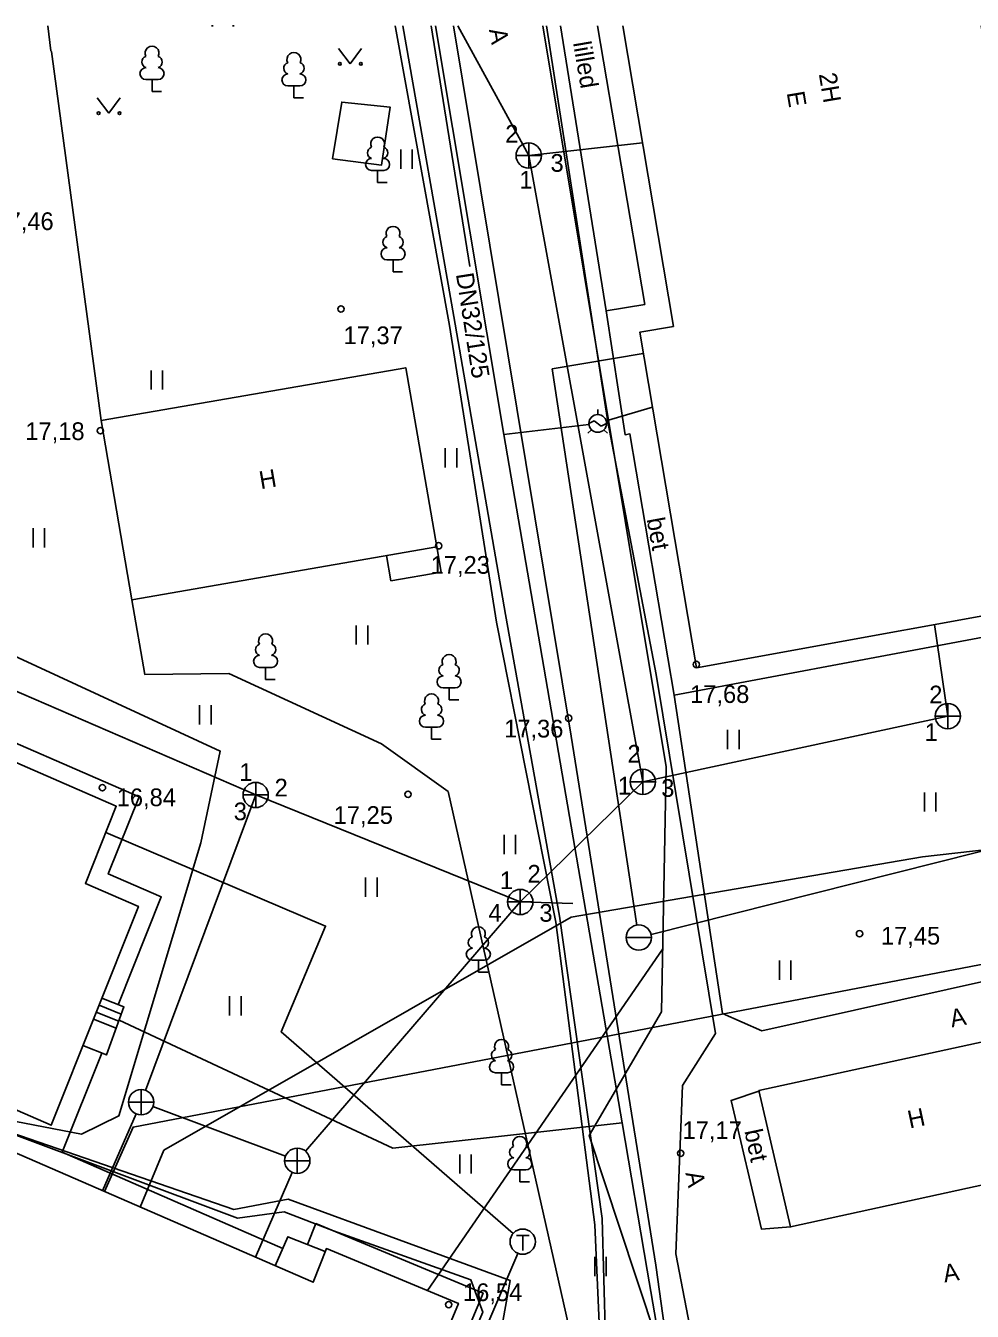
# Model space of a CAD drawing. Extents: x 713540 to 713867, y 6589774 to 6590061.
# Drawn here: x 713614.3 to 713651.7, y 6590009.8 to 6590060.6 of the extents above; entities that cross this region are included whole.
import ezdxf

# ---------------------------------------------------------------- set-up
doc = ezdxf.new("R2010")
doc.units = 0
for name, color, linetype in [('AED', 7, 'Continuous'), ('HALJASTUS', 7, 'Continuous'), ('HOONE', 7, 'Continuous'), ('HOONEDET', 7, 'Continuous'), ('KKAEV', 7, 'Continuous'), ('KORGUS', 7, 'Continuous'), ('KTRASS', 7, 'Continuous'), ('MPKAABEL', 7, 'Continuous'), ('PUU', 7, 'Continuous'), ('SITRASS', 7, 'Continuous'), ('TEE', 7, 'Continuous'), ('TKAEV', 7, 'Continuous'), ('TORU NR', 7, 'Continuous'), ('TTRASS', 7, 'Continuous'), ('VKAEV', 7, 'Continuous'), ('VTRASS', 7, 'Continuous')]:
    doc.layers.add(name, color=color, linetype=linetype)

msp = doc.modelspace()

# ---------------------------------------------------------------- linework, layer by layer
at = {"layer": 'AED'}
for points in [[(713617.266, 6590045.028), (713615.306, 6590059.611), (713615.285, 6590059.641), (713615.156, 6590060.636)], [(713618.488, 6590037.946), (713619.001, 6590034.99), (713622.312, 6590035.031), (713628.353, 6590032.257), (713630.993, 6590030.365), (713635.85, 6590008.82)]]:
    msp.add_lwpolyline(points, dxfattribs=at)
at = {"layer": 'HALJASTUS'}
for p, q in [((713626.647, 6590059.737), (713627.11, 6590059.13)), ((713627.11, 6590059.13), (713627.556, 6590059.737)), ((713617.107, 6590057.787), (713617.57, 6590057.18)), ((713617.57, 6590057.18), (713618.016, 6590057.787)), ((713629.111, 6590055.745), (713629.111, 6590054.984)), ((713629.567, 6590055.745), (713629.567, 6590054.984)), ((713619.246, 6590047.013), (713619.246, 6590046.252)), ((713619.701, 6590047.013), (713619.701, 6590046.252)), ((713630.872, 6590043.942), (713630.872, 6590043.181)), ((713631.327, 6590043.942), (713631.327, 6590043.181)), ((713614.579, 6590040.772), (713614.579, 6590040.011)), ((713615.035, 6590040.772), (713615.035, 6590040.011)), ((713627.351, 6590036.937), (713627.351, 6590036.176)), ((713627.806, 6590036.937), (713627.806, 6590036.176)), ((713621.164, 6590033.778), (713621.164, 6590033.017)), ((713621.619, 6590033.778), (713621.619, 6590033.017)), ((713642.032, 6590032.802), (713642.032, 6590032.041)), ((713642.488, 6590032.802), (713642.488, 6590032.041)), ((713649.814, 6590030.335), (713649.814, 6590029.574)), ((713650.269, 6590030.335), (713650.269, 6590029.574)), ((713633.198, 6590028.657), (713633.198, 6590027.895)), ((713633.653, 6590028.657), (713633.653, 6590027.895)), ((713627.724, 6590026.973), (713627.724, 6590026.212)), ((713628.179, 6590026.973), (713628.179, 6590026.212)), ((713644.082, 6590023.687), (713644.082, 6590022.925)), ((713644.537, 6590023.687), (713644.537, 6590022.925)), ((713622.348, 6590022.28), (713622.348, 6590021.519)), ((713622.803, 6590022.28), (713622.803, 6590021.519)), ((713631.444, 6590016.028), (713631.444, 6590015.267)), ((713631.899, 6590016.028), (713631.899, 6590015.267)), ((713636.784, 6590011.978), (713636.784, 6590011.217)), ((713637.239, 6590011.978), (713637.239, 6590011.217))]:
    msp.add_line(p, q, dxfattribs=at)
msp.add_lwpolyline([(713631.848, 6590051.113), (713630.32, 6590060.636)], dxfattribs=at)
for centre in [(713626.709, 6590059.13), (713627.538, 6590059.13), (713617.169, 6590057.18), (713617.998, 6590057.18)]:
    msp.add_circle(centre, 0.055, dxfattribs=at)
for centre in [(713621.669, 6590060.68), (713622.498, 6590060.68)]:
    msp.add_arc(centre, 0.055, 232.8853, 307.1147, dxfattribs=at)
at = {"layer": 'HOONE'}
for p, q in [((713636.55, 6590044.916), (713636.762, 6590045.022)), ((713636.762, 6590045.022), (713637.039, 6590044.814)), ((713636.9, 6590045.268), (713636.9, 6590045.465)), ((713636.653, 6590044.67), (713636.513, 6590044.531)), ((713637.039, 6590044.814), (713637.25, 6590044.92)), ((713637.148, 6590044.67), (713637.287, 6590044.531))]:
    msp.add_line(p, q, dxfattribs=at)
for points in [[(713630.482, 6590060.636), (713633.183, 6590044.481), (713637.86, 6590017.28), (713638.858, 6590011.457), (713641.66, 6589995.12)], [(713637.89, 6590060.636), (713639.902, 6590048.748)], [(713639.902, 6590048.748), (713638.559, 6590048.521), (713640.803, 6590035.264), (713657.339, 6590038.264), (713655.499, 6590048.497), (713654.156, 6590048.27), (713652.063, 6590060.636)], [(713617.266, 6590045.028), (713629.313, 6590047.119), (713630.535, 6590040.036), (713618.488, 6590037.946), (713617.266, 6590045.028)], [(713637.236, 6590045.018), (713639.06, 6590045.56)], [(713633.183, 6590044.481), (713636.553, 6590044.877)], [(713613.137, 6590018.115), (713615.293, 6590017.178), (713618.744, 6590025.83), (713616.649, 6590026.74), (713617.865, 6590029.789), (713611.861, 6590032.397)], [(713616.549, 6590020.329), (713617.479, 6590019.958), (713618.167, 6590021.858), (713617.298, 6590022.205)], [(713617.978, 6590021.334), (713628.8, 6590016.27), (713637.86, 6590017.28)], [(713643.269, 6590018.555), (713655.327, 6590021.172), (713656.52, 6590015.784), (713644.523, 6590013.163), (713643.269, 6590018.555)], [(713611.945, 6590002.466), (713620.997, 6589998.591), (713623.828, 6590005.205), (713628.509, 6590003.201), (713631.396, 6590010.137), (713626.176, 6590012.308), (713625.646, 6590010.977), (713612.515, 6590016.682)], [(713624.152, 6590011.626), (713624.651, 6590012.773), (713626.127, 6590012.184)]]:
    msp.add_lwpolyline(points, dxfattribs=at)
msp.add_circle((713636.9, 6590044.918), 0.35, dxfattribs=at)
at = {"layer": 'HOONEDET'}
for p, q in [((713617.963, 6590021.294), (713617.075, 6590021.648)), ((713618.065, 6590021.576), (713617.187, 6590021.926)), ((713617.861, 6590021.011), (713616.964, 6590021.369))]:
    msp.add_line(p, q, dxfattribs=at)
msp.add_lwpolyline([(713625.431, 6590012.462), (713625.762, 6590013.293), (713632.366, 6590010.546), (713628.89, 6590002.231), (713623.97, 6590004.19)], dxfattribs=at)
at = {"layer": 'KKAEV'}
for p, q in [((713634.172, 6590055.004), (713634.172, 6590056.004)), ((713633.672, 6590055.504), (713634.672, 6590055.504)), ((713650.741, 6590032.85), (713650.741, 6590033.85)), ((713650.241, 6590033.35), (713651.241, 6590033.35)), ((713638.683, 6590030.252), (713638.683, 6590031.252)), ((713638.183, 6590030.752), (713639.183, 6590030.752)), ((713622.878, 6590030.232), (713623.878, 6590030.232)), ((713623.378, 6590029.732), (713623.378, 6590030.732)), ((713633.839, 6590025.503), (713633.839, 6590026.503)), ((713633.339, 6590026.003), (713634.339, 6590026.003)), ((713618.849, 6590017.591), (713618.849, 6590018.591)), ((713618.349, 6590018.091), (713619.349, 6590018.091)), ((713625.024, 6590015.276), (713625.024, 6590016.276)), ((713624.524, 6590015.776), (713625.524, 6590015.776))]:
    msp.add_line(p, q, dxfattribs=at)
for centre in [(713634.172, 6590055.504), (713650.741, 6590033.35), (713638.683, 6590030.752), (713623.378, 6590030.232), (713633.839, 6590026.003), (713618.849, 6590018.091), (713625.024, 6590015.776)]:
    msp.add_circle(centre, 0.5, dxfattribs=at)
at = {"layer": 'KORGUS'}
for centre in [(713626.75, 6590049.44), (713617.24, 6590044.63), (713630.61, 6590040.08), (713640.8, 6590035.39), (713635.75, 6590033.27), (713617.32, 6590030.52), (713629.4, 6590030.26), (713647.25, 6590024.75), (713640.18, 6590016.07), (713631.01, 6590010.09)]:
    msp.add_circle(centre, 0.125, dxfattribs=at)
at = {"layer": 'KTRASS'}
for p, q in [((713634.172, 6590055.504), (713631.371, 6590060.636)), ((713634.172, 6590055.504), (713638.674, 6590056.003)), ((713638.683, 6590030.752), (713634.172, 6590055.504)), ((713607.872, 6590036.944), (713623.378, 6590030.232)), ((713650.741, 6590033.35), (713650.209, 6590036.971)), ((713638.683, 6590030.752), (713650.741, 6590033.35)), ((713633.839, 6590026.003), (713638.683, 6590030.752)), ((713623.378, 6590030.232), (713619.024, 6590018.559)), ((713623.378, 6590030.232), (713633.839, 6590026.003)), ((713633.839, 6590026.003), (713625.351, 6590016.154)), ((713633.839, 6590026.003), (713635.913, 6590025.949))]:
    msp.add_line(p, q, dxfattribs=at)
for points in [[(713618.65, 6590017.632), (713617.329, 6590014.591)], [(713619.317, 6590017.915), (713624.556, 6590015.951)], [(713624.825, 6590015.317), (713623.369, 6590011.966)]]:
    msp.add_lwpolyline(points, dxfattribs=at)
at = {"layer": 'MPKAABEL'}
for points in [[(713634.872, 6590060.636), (713637.296, 6590044.981), (713639.214, 6590034.99), (713641.55, 6590020.81), (713640.247, 6590018.756), (713639.99, 6590012.096), (713640.67, 6590008.54), (713653.54, 6589985.5)], [(713563.12, 6590039.09), (713578.092, 6590032.827), (713580.05, 6590031.785), (713583.09, 6590031.071), (713588.688, 6590044.404), (713590.239, 6590045.736), (713594.584, 6590044.316), (713608.321, 6590038.279), (713621.981, 6590031.97), (713621.208, 6590028.335), (713617.972, 6590017.545), (713616.488, 6590016.829), (713613.482, 6590017.411)], [(713613.314, 6590017.025), (713622.509, 6590013.848), (713624.668, 6590014.258), (713633.443, 6590011.043), (713632.914, 6590008.103), (713628.469, 6589990.573), (713626.542, 6589984.315), (713631.711, 6589980.868), (713636.285, 6589978.421)], [(713631.696, 6590008.26), (713632.361, 6590009.786), (713631.878, 6590011.07), (713626.458, 6590013.001), (713624.501, 6590013.754), (713622.661, 6590013.508), (713613.306, 6590017.006)]]:
    msp.add_lwpolyline(points, dxfattribs=at)
at = {"layer": 'PUU'}
for p, q in [((713619.52, 6590058.505), (713619.04, 6590058.505)), ((713619.28, 6590058.03), (713619.28, 6590058.505)), ((713625.13, 6590058.255), (713624.65, 6590058.255)), ((713624.89, 6590057.78), (713624.89, 6590058.255)), ((713619.66, 6590058.03), (713619.28, 6590058.03)), ((713625.27, 6590057.78), (713624.89, 6590057.78)), ((713628.44, 6590054.915), (713627.96, 6590054.915)), ((713628.2, 6590054.44), (713628.2, 6590054.915)), ((713628.58, 6590054.44), (713628.2, 6590054.44)), ((713629.049, 6590051.383), (713628.569, 6590051.383)), ((713628.809, 6590050.908), (713628.809, 6590051.383)), ((713629.189, 6590050.908), (713628.809, 6590050.908)), ((713624.011, 6590035.276), (713623.531, 6590035.276)), ((713623.771, 6590034.801), (713623.771, 6590035.276)), ((713624.151, 6590034.801), (713623.771, 6590034.801)), ((713631.265, 6590034.464), (713630.785, 6590034.464)), ((713631.025, 6590033.989), (713631.025, 6590034.464)), ((713631.405, 6590033.989), (713631.025, 6590033.989)), ((713630.571, 6590032.909), (713630.091, 6590032.909)), ((713630.331, 6590032.434), (713630.331, 6590032.909)), ((713630.711, 6590032.434), (713630.331, 6590032.434)), ((713632.422, 6590023.699), (713631.942, 6590023.699)), ((713632.182, 6590023.224), (713632.182, 6590023.699)), ((713632.562, 6590023.224), (713632.182, 6590023.224)), ((713633.339, 6590019.252), (713632.859, 6590019.252)), ((713633.099, 6590018.777), (713633.099, 6590019.252)), ((713633.479, 6590018.777), (713633.099, 6590018.777)), ((713634.059, 6590015.417), (713633.579, 6590015.417)), ((713633.819, 6590014.942), (713633.819, 6590015.417)), ((713634.199, 6590014.942), (713633.819, 6590014.942))]:
    msp.add_line(p, q, dxfattribs=at)
for centre, radius, start, end in [((713619.28, 6590059.55), 0.277, 332.5799, 207.4201), ((713619.11, 6590059.203), 0.233, 109.0217, 253.1415), ((713619.45, 6590059.203), 0.233, 286.8508, 70.9859), ((713624.89, 6590059.3), 0.277, 332.5799, 207.4201), ((713619.043, 6590058.742), 0.238, 90.0016, 269.3953), ((713619.517, 6590058.742), 0.238, 270.6047, 89.9984), ((713624.653, 6590058.492), 0.238, 90.0016, 269.3953), ((713624.72, 6590058.953), 0.233, 109.0217, 253.1415), ((713625.06, 6590058.953), 0.233, 286.8508, 70.9859), ((713625.127, 6590058.492), 0.238, 270.6047, 89.9984), ((713628.2, 6590055.96), 0.277, 332.5799, 207.4201), ((713628.03, 6590055.613), 0.233, 109.0217, 253.1415), ((713628.37, 6590055.613), 0.233, 286.8508, 70.9859), ((713627.963, 6590055.152), 0.238, 90.0016, 269.3953), ((713628.437, 6590055.152), 0.238, 270.6047, 89.9984), ((713628.809, 6590052.428), 0.277, 332.5799, 207.4201), ((713628.638, 6590052.081), 0.233, 109.0217, 253.1415), ((713628.979, 6590052.081), 0.233, 286.8508, 70.9859), ((713628.571, 6590051.62), 0.238, 90.0016, 269.3953), ((713629.046, 6590051.62), 0.238, 270.6047, 89.9984), ((713623.771, 6590036.321), 0.277, 332.5799, 207.4201), ((713623.601, 6590035.974), 0.233, 109.0217, 253.1415), ((713623.941, 6590035.974), 0.233, 286.8508, 70.9859), ((713623.533, 6590035.514), 0.238, 90.0016, 269.3953), ((713624.008, 6590035.514), 0.238, 270.6047, 89.9984), ((713630.854, 6590035.162), 0.233, 109.0217, 253.1415), ((713631.025, 6590035.509), 0.277, 332.5799, 207.4201), ((713631.195, 6590035.162), 0.233, 286.8508, 70.9859), ((713630.787, 6590034.702), 0.238, 90.0016, 269.3953), ((713631.262, 6590034.702), 0.238, 270.6047, 89.9984), ((713630.161, 6590033.607), 0.233, 109.0217, 253.1415), ((713630.331, 6590033.954), 0.277, 332.5799, 207.4201), ((713630.501, 6590033.607), 0.233, 286.8508, 70.9859), ((713630.093, 6590033.147), 0.238, 90.0016, 269.3953), ((713630.568, 6590033.147), 0.238, 270.6047, 89.9984), ((713632.182, 6590024.744), 0.277, 332.5799, 207.4201), ((713631.944, 6590023.937), 0.238, 90.0016, 269.3953), ((713632.012, 6590024.397), 0.233, 109.0217, 253.1415), ((713632.352, 6590024.397), 0.233, 286.8508, 70.9859), ((713632.419, 6590023.937), 0.238, 270.6047, 89.9984), ((713632.929, 6590019.95), 0.233, 109.0217, 253.1415), ((713633.099, 6590020.297), 0.277, 332.5799, 207.4201), ((713633.269, 6590019.95), 0.233, 286.8508, 70.9859), ((713632.861, 6590019.49), 0.238, 90.0016, 269.3953), ((713633.336, 6590019.49), 0.238, 270.6047, 89.9984), ((713633.819, 6590016.462), 0.277, 332.5799, 207.4201), ((713633.649, 6590016.114), 0.233, 109.0217, 253.1415), ((713633.989, 6590016.114), 0.233, 286.8508, 70.9859), ((713633.581, 6590015.654), 0.238, 90.0016, 269.3953), ((713634.056, 6590015.654), 0.238, 270.6047, 89.9984)]:
    msp.add_arc(centre, radius, start, end, dxfattribs=at)
at = {"layer": 'SITRASS'}
for points in [[(713634.735, 6590060.636), (713639.6, 6590031.34), (713639.42, 6590021.66), (713636.56, 6590016.77), (713638.404, 6590011.201), (713640.18, 6590005.84), (713646.71, 6589990.97), (713657.77, 6589965.9)], [(713617.4, 6590014.56), (713618.53, 6590017.11), (713661.613, 6590025.367)], [(713639.47, 6590024.15), (713630.174, 6590010.645)]]:
    msp.add_lwpolyline(points, dxfattribs=at)
at = {"layer": 'TEE'}
for points in [[(713614.57, 6589999.34), (713613.707, 6589997.19), (713603.922, 6590001.326), (713591.825, 6589974.045), (713621.261, 6589961.576), (713622.688, 6589963.147), (713630.481, 6589979.098), (713635.632, 6589979.743), (713638.264, 6589986.883), (713641.401, 6589995.818), (713639.191, 6590011.645), (713635.853, 6590032.559), (713631.194, 6590060.636)], [(713635.435, 6590060.636), (713637.235, 6590049.364)], [(713637.235, 6590049.364), (713638.76, 6590049.623), (713636.896, 6590060.636)], [(713653.066, 6590060.636), (713654.979, 6590049.333), (713656.159, 6590049.533), (713658.178, 6590037.604), (713639.918, 6590034.172), (713638.17, 6590044.505), (713637.984, 6590044.473), (713637.235, 6590049.364)], [(713626.42, 6590055.37), (713628.35, 6590055.12), (713628.69, 6590057.42), (713626.78, 6590057.62), (713626.42, 6590055.37)], [(713628.552, 6590039.692), (713628.724, 6590038.698), (713630.707, 6590039.041), (713630.535, 6590040.036)], [(713643.388, 6590020.908), (713641.835, 6590021.598), (713639.918, 6590034.172)], [(713610.71, 6590031.887), (713611.313, 6590033.399), (713618.766, 6590030.16), (713617.55, 6590027.111), (713619.646, 6590026.201), (713617.948, 6590021.945)], [(713643.388, 6590020.908), (713656.207, 6590023.767), (713660.498, 6590001.178), (713658.504, 6590000.777), (713648.984, 6589998.66), (713647.543, 6589998.927), (713645.546, 6590001.73), (713644.549, 6590006.589), (713645.573, 6590007.272)], [(713624.451, 6590012.314), (713615.73, 6590016.116), (713617.292, 6590020.032)], [(713643.313, 6590018.546), (713642.173, 6590018.161), (713643.374, 6590013.075), (713644.523, 6590013.163)]]:
    msp.add_lwpolyline(points, dxfattribs=at)
at = {"layer": 'TKAEV'}
for p, q in [((713633.684, 6590012.828), (713634.184, 6590012.828)), ((713633.934, 6590012.228), (713633.934, 6590012.828))]:
    msp.add_line(p, q, dxfattribs=at)
msp.add_circle((713633.934, 6590012.578), 0.5, dxfattribs=at)
at = {"layer": 'TTRASS'}
for points in [[(713628.896, 6590060.636), (713628.908, 6590060.564), (713631.035, 6590048.786), (713632.894, 6590037.061), (713635.242, 6590025.21), (713636.781, 6590013.249), (713637.307, 6590001.316), (713637.157, 6589996.645), (713637.245, 6589996.6), (713639.784, 6589996.778), (713639.911, 6589996.659), (713640.338, 6589988.697), (713640.169, 6589976.679), (713640.253, 6589976.609), (713650.804, 6589971.182), (713650.915, 6589970.999), (713652.857, 6589965.719), (713652.647, 6589965.295)], [(713629.199, 6590060.636), (713631.21, 6590049.147), (713633.256, 6590037.367), (713635.386, 6590025.437), (713637.081, 6590013.496), (713637.406, 6590001.507), (713637.495, 6589997.061), (713637.616, 6589996.981), (713640.19, 6589997.018), (713640.241, 6589996.932), (713640.549, 6589988.818), (713640.423, 6589976.86), (713640.479, 6589976.779), (713651.149, 6589971.354), (713651.264, 6589971.081), (713653.226, 6589965.534), (713653.017, 6589965.111)], [(713617.448, 6590028.744), (713626.14, 6590025.05), (713624.39, 6590020.87), (713633.557, 6590012.906)], [(713633.747, 6590012.114), (713624.389, 6589990.298)]]:
    msp.add_lwpolyline(points, dxfattribs=at)
at = {"layer": 'VKAEV'}
msp.add_line((713638.023, 6590024.599), (713639.023, 6590024.599), dxfattribs=at)
msp.add_circle((713638.523, 6590024.599), 0.5, dxfattribs=at)
at = {"layer": 'VTRASS'}
for points in [[(713638.702, 6590047.678), (713635.1, 6590047.07), (713638.448, 6590025.093)], [(713639.008, 6590024.721), (713664.837, 6590031.227)], [(713664.208, 6590029.493), (713663.589, 6590029.373), (713663.438, 6590029.34), (713663.119, 6590029.299), (713649.744, 6590027.784), (713635.847, 6590025.4)], [(713618.816, 6590013.945), (713619.75, 6590016.19), (713635.847, 6590025.4)]]:
    msp.add_lwpolyline(points, dxfattribs=at)

# ---------------------------------------------------------------- texts
at = {"layer": 'HALJASTUS'}
msp.add_text('lilled', height=0.7, rotation=279.6061, dxfattribs=at).set_placement((713635.923, 6590059.962))
at = {"layer": 'HOONE'}
for s, rotation, p in [('2H', 279.6065, (713645.639, 6590058.723)), ('E', 279.6065, (713644.369, 6590057.988)), ('H', 9.8436, (713623.581, 6590042.316)), ('H', 12.0248, (713649.234, 6590017.047))]:
    msp.add_text(s, height=0.7, rotation=rotation, dxfattribs=at).set_placement(p)
at = {"layer": 'HOONEDET'}
for rotation, p in [(280.5067, (713638.83, 6590041.136)), (281.9241, (713642.695, 6590016.952))]:
    msp.add_text('bet', height=0.7, rotation=rotation, dxfattribs=at).set_placement(p)
at = {"layer": 'KORGUS'}
for s, p in [('17,46', (713613.05, 6590052.56)), ('17,37', (713626.851, 6590048.05)), ('17,18', (713614.272, 6590044.26)), ('17,23', (713630.296, 6590038.975)), ('17,68', (713640.552, 6590033.87)), ('17,36', (713633.2, 6590032.505)), ('16,84', (713617.884, 6590029.79)), ('17,25', (713626.461, 6590029.09)), ('17,45', (713648.096, 6590024.32)), ('17,17', (713640.253, 6590016.635)), ('16,54', (713631.574, 6590010.23))]:
    msp.add_text(s, height=0.7, dxfattribs=at).set_placement(p)
at = {"layer": 'TEE'}
for rotation, p in [(280.4261, (713632.598, 6590060.477)), (11.0879, (713650.895, 6590021.042)), (281.4795, (713640.366, 6590015.293)), (9.4573, (713650.61, 6590010.961))]:
    msp.add_text('A', height=0.7, rotation=rotation, dxfattribs=at).set_placement(p)
at = {"layer": 'TORU NR'}
for s, p in [('2', (713633.244, 6590056.016)), ('3', (713635.034, 6590054.863)), ('1', (713633.805, 6590054.196)), ('2', (713650.007, 6590033.853)), ('1', (713649.825, 6590032.366)), ('2', (713638.076, 6590031.509)), ('1', (713622.731, 6590030.789)), ('2', (713624.127, 6590030.174)), ('1', (713637.696, 6590030.25)), ('3', (713639.411, 6590030.159)), ('3', (713622.511, 6590029.234)), ('1', (713633.032, 6590026.511)), ('2', (713634.124, 6590026.769)), ('4', (713632.577, 6590025.221)), ('3', (713634.594, 6590025.221))]:
    msp.add_text(s, height=0.7, dxfattribs=at).set_placement(p)
at = {"layer": 'TTRASS'}
msp.add_text('DN32/125', height=0.7, rotation=278.9146, dxfattribs=at).set_placement((713631.291, 6590050.82))

doc.saveas('drawing.dxf')
